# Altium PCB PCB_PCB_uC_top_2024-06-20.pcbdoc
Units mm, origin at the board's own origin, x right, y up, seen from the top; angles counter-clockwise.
Board outline 106.02 x 86.66 mm, 2 copper layers (Top Layer, Bottom Layer); 56 components, 53 nets, 220 pads, 9 vias.
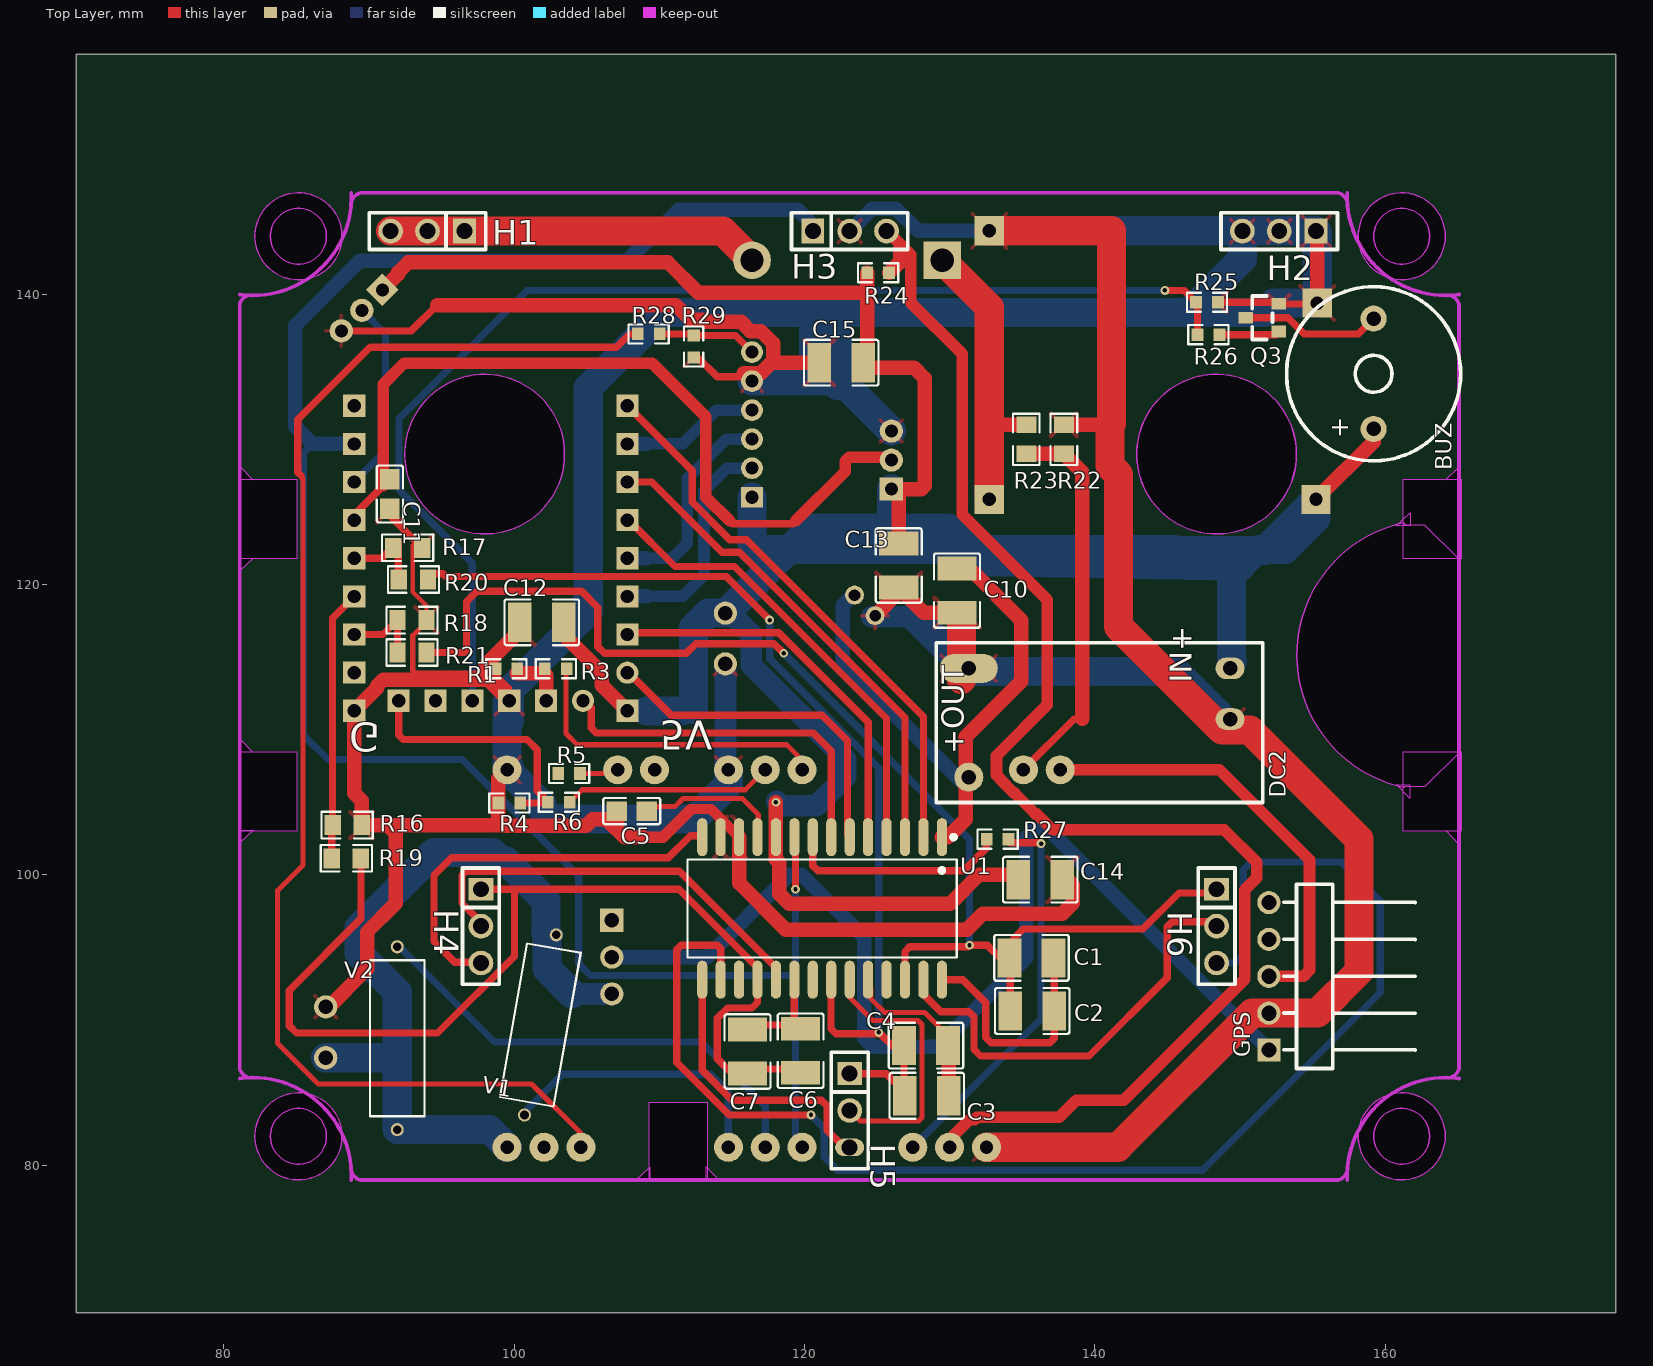
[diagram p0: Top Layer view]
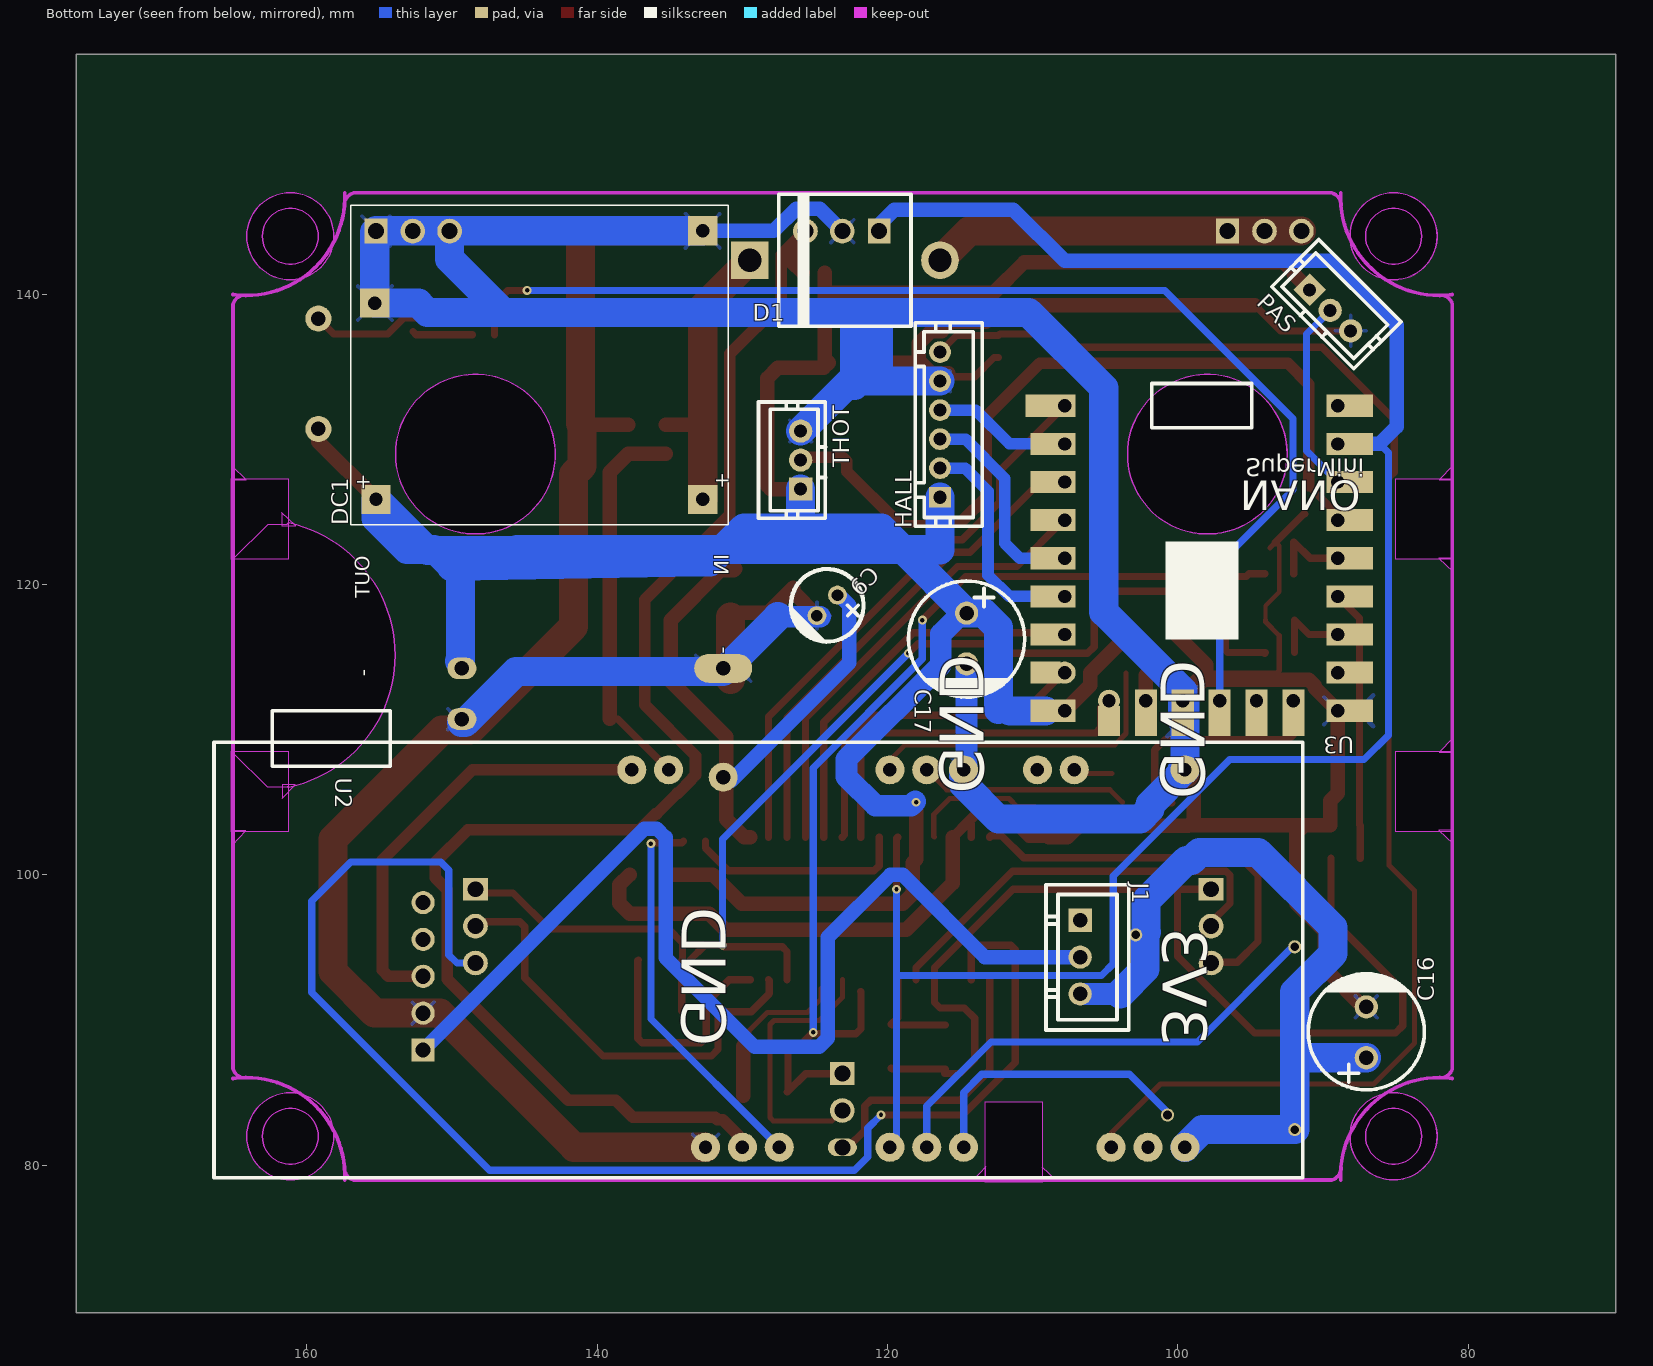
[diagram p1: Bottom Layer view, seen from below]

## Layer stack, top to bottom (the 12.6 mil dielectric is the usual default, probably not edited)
Top Layer: signal copper (thickness not stored)
Dielectric: dielectric 0.32, FR-4, Dk 4.8
Bottom Layer: signal copper (thickness not stored)

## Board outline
175.87,69.85 69.85,69.85 69.85,156.515 175.87,156.515
cut-out: 88.141,81.991 cw(c85.141,81.991) 82.141,81.991 cw(c85.141,81.991)
cut-out: 164.141,143.991 cw(c161.141,143.991) 158.141,143.991 cw(c161.141,143.991)
cut-out: 164.141,81.991 cw(c161.141,81.991) 158.141,81.991 cw(c161.141,81.991)
cut-out: 88.141,143.991 cw(c85.141,143.991) 82.141,143.991 cw(c85.141,143.991)
cut-out: 103.468,128.981 cw(c97.968,128.981) 92.468,128.981 cw(c97.968,128.981)
cut-out: 153.887,128.981 cw(c148.387,128.981) 142.887,128.981 cw(c148.387,128.981)
cut-out: 81.014,127.241 85.014,127.241 85.014,121.772 81.014,121.772
cut-out: 161.246,127.241 165.246,127.241 165.246,121.772 161.246,121.772
cut-out: 109.303,84.322 113.303,84.322 113.303,78.853 109.303,78.853
cut-out: 81.014,108.475 85.014,108.475 85.014,103.006 81.014,103.006
cut-out: 161.246,108.475 165.246,108.475 165.246,103.006 161.246,103.006
cut-out: 159.214,143.991 cw(c161.141,143.991) 163.068,143.991 cw(c161.141,143.991)
cut-out: 83.214,143.991 cw(c85.141,143.991) 87.068,143.991 cw(c85.141,143.991)
cut-out: 83.214,81.991 cw(c85.141,81.991) 87.068,81.991 cw(c85.141,81.991)
cut-out: 159.214,81.991 cw(c161.141,81.991) 163.068,81.991 cw(c161.141,81.991)
cut-out: 161.338,106.07 cw(c161.246,106.158) 161.246,106.031 cw(c161.246,106.158) 161.218,106.034 cw(c163.246,115.138) 153.919,115.138 cw(c163.246,115.138) 161.218,124.242 cw(c161.246,124.118) 161.246,124.245 cw(c161.246,124.118) 161.373,124.123 162.694,124.123 165.088,121.728 165.088,108.416 162.743,106.07
cut-out: 81.991,127.203 81.089,127.203 81.089,128.158
cut-out: 81.057,120.91 81.057,121.813 82.011,121.813
cut-out: 81.057,102.165 81.057,103.067 82.011,103.067
cut-out: 81.985,108.438 81.083,108.438 81.083,109.392
cut-out: 114.142,78.923 113.239,78.923 113.239,79.878
cut-out: 109.342,79.852 109.342,78.949 108.387,78.949
cut-out: 165.12,128.112 165.12,127.209 164.166,127.209
cut-out: 164.191,103.042 165.094,103.042 165.094,102.088
cut-out: 160.794,106.217 161.697,106.217 161.697,105.263
cut-out: 161.723,124.958 161.723,124.055 160.769,124.055

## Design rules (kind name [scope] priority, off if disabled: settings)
BoardOutlineClearance Default [All] p0: genericclearance=0.254 ignorepadtopadclearanceinfootprint=FALSE except(0: Region-OutlineEdge Region-CutoutEdge Arc-SplitContinuation Track-SplitContinuation SMDPad-SplitContinuation THPad-SplitContinuation Via-SplitContinuation Fill-SplitContinuation Poly-SplitContinuation Region-SplitContinuation Text-SplitContinuation; 0.152: Track-OutlineEdge SMDPad-OutlineEdge THPad-OutlineEdge Via-OutlineEdge Fill-OutlineEdge Poly-OutlineEdge Text-OutlineEdge Track-CutoutEdge SMDPad-CutoutEdge THPad-CutoutEdge Via-CutoutEdge Fill-CutoutEdge)
Clearance Default [(InNet('T+') OR InNet('U_L') OR InNet('U_H') OR InNet('UO') OR InNet('V_L') OR InNet('V_H') OR InNet('VO') OR InNet('W_L') OR InNet('W_H') OR InNet('WO') OR InNet('NTC') OR InNet('GND') OR InNet('ISENSE') OR InNet('W_HIN') OR InNet('+5V') OR InNet('UOX') OR InNet('VOX') OR InNet('WOX') OR InNet('THOT') OR InNet('U_LIN') OR InNet('W_LIN') OR InNet('V_HIN') OR InNet('V_LIN') OR InNet('U_HIN') OR InNet('+12V') OR InNet('$1N2961') OR InNet('$1N3241') OR InNet('NRX') OR InNet('NTX') OR InNet('HALT') OR InNet('$1N11348') OR InNet('$1N11342') OR InNet('VSENSE') OR InNet('FAULT') OR InNet('DRX') OR InNet('$1N9478') OR InNet('HALL_W') OR InNet('HALL_V') OR InNet('HALL_U') OR InNet('$1N22834') OR InNet('ENBUZ') OR InNet('$1N22836') OR InNet('$1N27077') OR InNet('$1N27237') OR InNet('+3V3') OR InNet('$1N27595') OR InNet('$1N27524') OR InNet('$1N29131') OR InNet('PAS') OR InNet('TD+') OR InNet('MOTTEMP') OR InNet('$1N29431') OR InNet('GPS+'))] p1: gap=0.178 ignorepadtopadclearanceinfootprint=FALSE except(0: Region-Region Poly-Poly Region-Sheet; 0.152: SMDPad-Fill THPad-Fill Via-Fill Fill-Fill Track-Region SMDPad-Region THPad-Region Via-Region Fill-Region Track-Poly SMDPad-Poly THPad-Poly Via-Poly Fill-Poly Region-Poly Track-Text SMDPad-Text THPad-Text Via-Text Fill-Text Region-Text Poly-Text Text-Text Track-Sheet SMDPad-Sheet THPad-Sheet Via-Sheet Fill-Sheet Poly-Sheet Text-Sheet Track-Hole SMDPad-Hole THPad-Hole Via-Hole Fill-Hole Region-Hole Poly-Hole Text-Hole Sheet-Hole; 0.201: Track-Track Track-SMDPad SMDPad-SMDPad Track-THPad SMDPad-THPad THPad-THPad Track-Via SMDPad-Via THPad-Via Via-Via Track-Fill)
DiffPairsRouting differentialPair [All] p1: maxuncoupledlength=10 minlimit=5.9843 maxlimit=5.9843 mostfreqgap=5.9843 toplayer_minwidth=5 toplayer_prefwidth=10 toplayer_maxwidth=100 bottomlayer_minwidth=5 bottomlayer_prefwidth=10 bottomlayer_maxwidth=100
PasteMaskExpansion Common [All] p1: expansion=0
PlaneConnect Default [All] p1: planeconnectstyle=Relief reliefexpansion=0.508 reliefentries=4 reliefconductorwidth=0 reliefairgap=0.254
PolygonConnect copperRegion [All] p1: connectstyle=Relief reliefentries=4 reliefconductorwidth=11.811 polygonreliefangle="45 Angle" airgapwidth=11.811
PolygonConnect copperRegion1 [All] p1: connectstyle=Relief reliefentries=4 reliefconductorwidth=10 polygonreliefangle="90 Angle" airgapwidth=10
RoutingVias Default [All] p1: viastyle="Through Hole" holewidth=12.0078 minholewidth=12.0078 maxholewidth=2362.0078 width=24.0158 minwidth=24.0158 maxwidth=3937.9922
SolderMaskExpansion Common [All] p1: useseparateexpansions=TRUE expansion=2.0079 expansionbottom=2.0079
Width Default [All] p1: maxlimit=1000 minlimit=10 preferedwidth=10

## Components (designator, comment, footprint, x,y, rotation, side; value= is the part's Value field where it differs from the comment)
BUZ "HMB1275-05B" BUZ-TH_BD12.0-P7.60-D0.6-FD 159.207,134.518 r90 top
C1 "10uF(106) 50V" C1210 135.636,94.285 r0 top
C2 "10uF(106) 50V" C1210 135.687,90.627 r0 top
C3 "10uF(106) 50V" C1210 128.422,84.785 r0 top
C4 "10uF(106) 50V" C1210 128.372,88.24 r0 top
C5 "CC0805KRX7R9BB221" C0805 108.102,104.394 r0 top
C6 "10uF(106) 50V" C1210 119.736,87.884 r90 top
C7 "10uF(106) 50V" C1210 116.078,87.833 r90 top
C9 "RL1J100MC110A00CV0" CAP-TH_BD5.0-P2.00-D0.8-FD 124.155,118.567 r315 bottom
C10 "10uF(106) 50V" C1210 130.505,119.583 r90 top
C11 "30pF/100V" C0805 91.44,126.238 r270 top
C12 "10uF(106) 50V" C1210 101.905,117.399 r0 top
C13 "10uF(106) 50V" C1210 126.492,121.31 r90 top
C14 "10uF(106) 50V" C1210 136.246,99.67 r180 top
C15 "10uF(106) 50V" C1210 122.53,135.28 r0 top
C16 "ERR1CM681F12B35T" CAP-TH_BD8.0-P3.50-D0.6-FD 87.02,89.154 r90 bottom
C17 "ERR1CM681F12B35T" CAP-TH_BD8.0-P3.50-D0.6-FD 114.554,116.281 r270 bottom
D1 "10SQ050" R-6_BD8.9-L8.9-P12.90-D1.3-RD 122.936,142.342 r180 bottom locked
DC1 "LX8015_STEP_DOWN_DC_DC_MODULE" LX8015_STEP_DOWN_DC_DC_MODULE 131.978,125.12 r90 bottom locked
DC2 "DC_STEP_UP_BOOST_MINI_3_12V" dc_step_up_boost_mini_3_12v 131.318,106.731 r90 top
GPS "KH-2.54PH90-1X5P-L13.8" HDR-TH_5P-P2.54-H-M-W10.4-N 151.994,93.015 r90 top
H1 "PZ254-1-03-Z-8.5" HDR-TH_03P-P2.54-V-M 94.031,144.348 r180 top locked
H2 "PZ254-1-03-Z-8.5" HDR-TH_03P-P2.54-V-M 152.705,144.348 r180 top locked
H3 "PZ254-1-03-Z-8.5" HDR-TH_03P-P2.54-V-M 123.114,144.348 r0 top locked
H4 "PZ254-1-03-Z-8.5" HDR-TH_03P-P2.54-V-M 97.714,96.469 r270 top locked
H5 "PZ254-1-03-Z-8.5" hdr-th_03p-p2.54-v-m 123.114,83.769 r270 top locked
H6 "PZ254-1-03-Z-8.5" HDR-TH_03P-P2.54-V-M 148.387,96.469 r270 top locked
HALL "XD-PH-6A-G" CONN-TH_PH-6A_C722783 116.383,131.013 r90 bottom
J1 "ZX-XH2.54-3PZZ" CONN-TH_3P-P2.54_2501S-3P 106.731,94.336 r270 bottom
PAS "XD-PH-3A-G" CONN-TH_3P-P2.00_PH-3AK 89.51,138.887 r225 bottom
Q3 "SI2302" SOT-23_L2.9-W1.3-P1.90-LS2.4-BR 151.536,138.379 r0 top
R1 "0603WAF7502T5E" R0603 99.466,114.198 r180 top
R3 "0603WAF4701T5E" R0603 102.87,114.198 r180 top
R4 "0603WAF1801T5E" R0603 99.67,104.953 r0 top
R5 "0603WAF220JT5E" R0603 103.784,106.985 r180 top
R6 "0603WAF6800T5E" R0603 103.073,105.004 r0 top
R16 "AECR0805F43K0K9" R0805 88.494,103.429 r0 top
R17 "AECR0805F43K0K9" R0805 92.659,122.53 r0 top
R18 "AECR0805F43K0K9" R0805 92.964,117.551 r0 top
R19 "AECR0805F680KK9" R0805 88.443,101.143 r180 top
R20 "AECR0805F680KK9" R0805 93.066,120.345 r180 top
R21 "AECR0805F680KK9" R0805 92.964,115.316 r180 top
R22 "CR0805-FX-1802ELF" R0805 137.871,129.997 r90 top
R23 "AECR0805F680KK9" R0805 135.28,129.997 r270 top
R24 "0603WAF1002T5E" R0603 125.07,141.478 r0 top
R25 "0603WAF4703T5E" R0603 147.726,139.446 r0 top
R26 "0603WAF220JT5E" R0603 147.828,137.211 r0 top
R27 "0603WAF6800T5E" R0603 133.299,102.464 r180 top
R28 "0603WAF6800T5E" R0603 109.271,137.262 r180 top
R29 "0603WAF1801T5E" R0603 112.37,136.398 r270 top
THOT "XD-PH-3A-G" CONN-TH_3P-P2.00_PH-3AK 125.984,128.575 r90 bottom
U1 "6EDL04N06PT" PG-DSO-28_L18.2-W7.6-P1.27-LS10.3-BL 121.209,97.688 r180 top locked
U2 "LILYGO_ESP32_SIM800" LILYLGO_ESO32_SIM800L 137.617,107.239 r270 bottom locked
U3 "Arduino Nano Supermini 24P Small module" arduino_nano_supermini 107.798,111.303 r0 bottom locked
V1 "SW-200D 053" SW-TH_BD3.6-L10.6-LS12.6-D0.4 101.803,89.662 r80 top
V2 "SW-200D 053" SW-TH_BD3.6-L10.6-LS12.6-D0.4 91.948,88.748 r270 top

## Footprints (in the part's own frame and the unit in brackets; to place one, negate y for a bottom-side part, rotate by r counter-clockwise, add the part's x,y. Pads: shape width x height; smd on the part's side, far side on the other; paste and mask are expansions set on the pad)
arduino_nano_supermini [mil]
  rect 60x60 hole 36: 1(-620.28,-27.16) 2(-520.27,-27.16) 3(-420.27,-27.16) 4(-320.27,-27.16) 5(-220.27,-27.17) 7(0,0) 9(0,-206.79) 10(0,-310.19) 11(0,-413.58) 12(0,-516.98) 13(0,-620.37) 14(0,-723.77) 15(0,-827.16) 16(-740.55,0) 17(-740.55,-103.4) 18(-740.55,-206.79) 19(-740.55,-310.19) 20(-740.55,-413.58) 21(-740.55,-516.98) 22(-740.55,-620.37) 23(-740.55,-723.77) 24(-740.55,-827.16)
  rect 60x81.5 smd: 1(-620.27,27.16) 2(-520.27,27.17) 3(-420.27,27.17) 4(-320.27,27.17) 5(-220.27,27.17) 6(-120.27,27.16)
  round 60 hole 36: 6(-120.27,-27.17) 8(0,-103.4)
  rect 81.5x60 smd: 7(51.97,0) 8(51.97,-103.4) 9(51.97,-206.79) 10(51.97,-310.19) 11(51.97,-413.58) 12(51.97,-516.98) 13(51.97,-620.37) 14(51.97,-723.77) 15(65.55,-827.16) 16(-794.88,0) 17(-794.88,-103.4) 18(-794.88,-206.79) 19(-794.88,-310.19) 20(-794.88,-413.58) 21(-794.88,-516.98) 22(-794.88,-620.37) 23(-794.88,-723.77) 24(-794.88,-827.16)
  silkscreen extent -507,-888 -236,-194
BUZ-TH_BD12.0-P7.60-D0.6-FD [mm]
  round 1.8 hole 1: 1(-3.8,0) 2(3.8,0)
  silkscreen extent -6,-6 6,6
C0805 [mm]
  rect 1.41x1.35 smd: 1(-1.03,0) 2(1.03,0)
  silkscreen extent -1.96,-0.9 1.96,0.9
C1210 [mm]
  rect 1.635x2.7 smd: 1(-1.517,0) 2(1.517,0)
  silkscreen extent -2.56,-1.58 2.56,1.58
CAP-TH_BD5.0-P2.00-D0.8-FD [mm]
  round 1.3 hole 0.8: 1(-1,0) 2(1,0)
  silkscreen extent -2.5,-2.5 2.5,2.5
CAP-TH_BD8.0-P3.50-D0.6-FD [mm]
  round 1.6 hole 1: 1(-1.75,0) 2(1.75,0)
  silkscreen extent -3.96,-4 4.04,4
CONN-TH_3P-P2.00_PH-3AK [mm]
  rect 1.6x1.6 hole 0.9: 1(-2,0)
  round 1.6 hole 0.9: 2(0,0) 3(2,0)
  silkscreen extent -4.01,-1.71 4.01,2.9
CONN-TH_3P-P2.54_2501S-3P [mm]
  rect 1.6x1.6 hole 1: 1(-2.54,0)
  round 1.6 hole 1: 2(0,0) 3(2.54,0)
  silkscreen extent -4.98,-2.35 5.02,3.35
CONN-TH_PH-6A_C722783 [mm]
  rect 1.4x1.5 hole 0.9: 1(-5,0)
  round 1.5 hole 0.9: 2(-3,0) 3(-1,0) 4(1,0) 5(3,0) 6(5,0)
  silkscreen extent -7,-2.9 7.01,1.7
dc_step_up_boost_mini_3_12v [mm]
  oval 1.5x2 hole 1: 1(7.5,-18) 2(4,-18)
  round 2 hole 1: 3(0,0)
  oval 2x4 hole 1: 4(7.5,0)
  silkscreen extent -1.75,-20.25 9.25,2.25
HDR-TH_03P-P2.54-V-M [mm]
  rect 1.575x1.7 hole 1.1: 1(-2.54,0)
  round 1.7 hole 1.1: 2(0,0) 3(2.54,0)
  silkscreen extent -4.01,-1.27 4.01,1.27
hdr-th_03p-p2.54-v-m [mm]
  rect 1.575x1.7 hole 1.1: 1(-2.54,0)
  round 1.7 hole 1.1: 2(0,0)
  oval 1.2x2 hole 1.1: 3(2.54,0)
  silkscreen extent -4.01,-1.27 4.01,1.27
HDR-TH_5P-P2.54-H-M-W10.4-N [mm]
  rect 1.6x1.6 hole 1.05: 1(-5.08,0)
  round 1.6 hole 1.05: 2(-2.54,0) 3(0,0) 4(2.54,0) 5(5.08,0)
  silkscreen extent -6.35,-10.08 6.35,-1.03
LILYLGO_ESO32_SIM800L [mm]
  round 2 hole 0.914: 1(0,30.48) 2(0,2.54) 3(0,27.94) 12(26,7.62) 14(26,10.16) 15(0,0) 18(0,17.78) 19(0,20.32) 25(26,17.78) 32(26,22.86) 33(26,20.32) 36(26,33.02) 40(26,38.1) 41(26,35.56) 42(26,5.08) 60(0,38.1) 61(0,22.86)
  silkscreen extent -4.06,-28.77 28.1,46.23
LX8015_STEP_DOWN_DC_DC_MODULE [mm]
  rect 2x2 hole 0.914: 1(0.75,0.75) 2(19.25,0.75) 3(0.75,23.25) 4(14.262,23.343)
  silkscreen extent -1,-1 21,25
PG-DSO-28_L18.2-W7.6-P1.27-LS10.3-BL [mm]
  oval 0.7x2.62 smd: 1(-8.255,-4.91) 2(-6.985,-4.91) 3(-5.715,-4.91) 4(-4.445,-4.91) 5(-3.175,-4.91) 6(-1.905,-4.91) 7(-0.635,-4.91) 8(0.635,-4.91) 9(1.905,-4.91) 10(3.175,-4.91) 11(4.445,-4.91) 12(5.715,-4.91) 13(6.985,-4.91) 14(8.255,-4.91) 15(8.255,4.91) 16(6.985,4.91) 17(5.715,4.91) 18(4.445,4.91) 19(3.175,4.91) 20(1.905,4.91) 21(0.635,4.91) 22(-0.635,4.91) 23(-1.905,4.91) 24(-3.175,4.91) 25(-4.445,4.91) 26(-5.715,4.91) 27(-6.985,4.91) 28(-8.255,4.91)
  silkscreen extent -9.28,-5.06 9.28,3.37
R0603 [mm]
  rect 0.806x0.864 smd: 1(-0.753,0) 2(0.753,0)
  silkscreen extent -1.39,-0.66 1.39,0.66
R0805 [mm]
  rect 1.133x1.377 smd: 1(-1,0) 2(1,0)
  silkscreen extent -1.76,-0.92 1.76,0.92
R-6_BD8.9-L8.9-P12.90-D1.3-RD [mm]
  rect 2.6x2.6 hole 1.6: 1(-6.55,0)
  round 2.6 hole 1.6: 2(6.55,0)
  silkscreen extent -4.55,-4.55 4.55,4.55
SOT-23_L2.9-W1.3-P1.90-LS2.4-BR [mm]
  rect 1x0.8 smd: 1(1.15,-0.95) 2(1.15,0.95) 3(-1.15,0)
  silkscreen extent -0.7,-1.5 0.7,1.5
SW-TH_BD3.6-L10.6-LS12.6-D0.4 [mm]
  round 0.9 hole 0.6: 1(-6.3,0) 2(6.3,0)
  silkscreen extent -5.38,-1.88 5.38,1.88

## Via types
v1: diameter 0.61, hole 0.305, Top Layer to Bottom Layer, 9 vias

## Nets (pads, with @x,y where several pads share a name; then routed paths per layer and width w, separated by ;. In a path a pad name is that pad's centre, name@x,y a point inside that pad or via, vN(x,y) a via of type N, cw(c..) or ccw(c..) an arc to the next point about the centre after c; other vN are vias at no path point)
$1N2961: C1.2 C2.2 U1.28 | length 16.5
  Top Layer w0.5: U1.28 130.896,92.778 132.488,91.186 132.488,88.796 132.842,88.443 136.906,88.443 137.204,88.741 C2.2 137.204,94.082 C1.2@137.153,94.132
$1N3241: C5.2 U1.11 | length 10.2
  Top Layer w0.35: C5.2 109.336,104.394 109.437,104.292 109.844,104.699 111.07,104.699 111.635,105.263 112.112,105.263 112.12,105.271 113.846,105.271 113.855,105.263 115.717,105.263 116.815,104.165 116.815,102.649 U1.11
$1N9478: R1.1 R3.2 U3.5 | length 3.9
  Top Layer w1: R1.1@100.169,113.894 102.066,113.894 102.203,113.757 U3.5@102.203,111.993
$1N11342: C6.2 C7.2 U1.20 | length 7
  Top Layer w0.5: C7.2@116.027,89.655 119.685,89.655 119.736,89.706 119.304,90.138 U1.20
$1N11348: C3.2 C4.2 U1.24 | length 11.6
  Top Layer w0.35: U1.24 124.384,92.372 124.573,92.183 124.573,91.467 125.526,90.515 128.281,90.515 129.539,89.257 129.539,88.894 C4.2@129.889,88.544
  Top Layer w1: C4.2 129.94,88.189 C3.2
$1N22834: Q3.1 R26.2 | length 4.2
  Top Layer w0.5: R26.2 152.468,137.211 Q3.1
$1N22836: BUZ.2 Q3.3 | length 9.7
  Top Layer w0.5: Q3.3 153.314,138.379 154.432,137.262 158.15,137.262 BUZ.2
$1N27077: R5.1 U2.1 | length 2.7
  Top Layer w0.35: R5.1 106.883,106.985 U2.1
$1N27237: R6.2 U2.19 | length 14.4
  Top Layer w0.35: R6.2 104.687,105.864 115.922,105.864 U2.19
$1N27524: U2.32 V1.1 | length 19.6
  Bottom Layer w0.5: V1.1 100.709,83.64 103.327,86.258 113.514,86.258 114.757,85.015 U2.32
$1N27595: R27.1 U2.14 | length 26.9
  Top Layer w0.5: R27.1@134.053,102.311 134.154,102.21 136.246,102.21 v1(136.296,102.159)
  Bottom Layer w0.5: U2.14 136.296,90.078 v1(136.296,102.159)
$1N29131: U2.33 V2.1 | length 32.7
  Bottom Layer w0.5: V2.1 92.1,95.048 98.654,88.494 112.878,88.494 117.297,84.074 U2.33
$1N29431: HALL.6 R28.1 R29.1 | length 6.9
  Top Layer w0.5: R28.1 112.259,137.262 R29.1 115.245,137.151 HALL.6
+3V3: C16.1 J1.3 U2.40 V1.2 V2.2 | length 55.1
  Bottom Layer w1: 102.157,96.069 102.159,96.068 102.26,95.966 102.36,95.866 V1.2
  Bottom Layer w1.5: 103.988,91.796 J1.3
  Bottom Layer w2: C16.1 91.84,87.404 91.948,87.296 ; U2.40 98.308,82.448 V2.2 91.948,87.296 ; 102.159,96.068 102.21,96.118 102.21,98.203 99.416,100.997 99.061,100.997 98.512,101.546 94.484,101.546 89.306,96.368 89.306,94.59 91.948,91.948 91.948,87.296 ; 102.26,95.966 102.26,93.523 103.988,91.796
+5V: BUZ.1 C12.2 C13.2 C14.2 C15.2 C17.1 DC1.3 DC2.1 HALL.1 PAS.1 R24.1 THOT.1 U1.10 U3.7 | length 232
  Top Layer w1: PAS.1 91.999,141.376 91.999,141.478 92.706,142.185 110.596,142.185 112.683,140.098 124.316,140.098 ; C12.2@103.27,116.688 106.036,113.922 106.036,113.065 U3.7@107.798,111.303 ; v1(118.034,105.004) U1.10 118.034,101.067 118.254,100.847 118.254,98.714 118.964,98.004 130.029,98.004 132.05,100.025 C14.2@134.728,100.025 ; R24.1 124.316,140.098 ; C13.2 126.492,126.067 THOT.1 128.048,126.575 128.27,126.797 128.27,134.214 127.563,134.921 124.407,134.921 C15.2 124.316,135.55 124.316,140.098 ; DC1.3@155.228,125.87 159.207,129.849 BUZ.1
  Bottom Layer w1: U3.7@107.798,111.303 U3.7@109.118,111.303
  Bottom Layer w1.5: C17.1@114.887,118.031 116.332,116.586 116.332,114.452 122.829,107.956 122.829,106.761 120.823,104.755 118.384,104.755 v1@118.085,105.054
  Bottom Layer w2: U3.7@109.118,111.303 111.557,111.303 ; 112.37,111.404 112.37,117.043 113.358,118.031 C17.1 ; C17.1@114.91,118.031 114.887,118.031 C17.1 ; HALL.1@116.383,126.013 116.383,122.377 116.43,122.424 118.947,122.424 ; THOT.1 125.984,123.901 ; 132.842,121.564 132.74,121.564 ; DC2.1@149.47,114.739 149.42,114.79 149.42,120.722 149.958,121.261 150.008,121.261 ; 150.063,121.26 150.009,121.261 ; 151.142,122.329 151.237,122.424 151.782,122.424 ; 151.989,122.631 155.228,125.87 155.228,124.545 153.107,122.424 151.989,122.424 ; C17.1 118.947,122.424 ; 118.947,122.424 126.026,122.424 ; 118.947,122.424 120.424,123.901 125.984,123.901 ; 125.984,123.901 129.896,123.901 131.373,122.424 ; 125.984,123.901 125.984,122.466 126.026,122.424 ; 126.026,122.424 131.373,122.424 ; 131.373,122.424 132.232,121.564 132.74,121.564 ; 131.373,122.424 145.537,122.424 145.631,122.329 151.077,122.329 ; 132.74,121.564 150.008,121.261 ; 150.009,121.261 151.077,122.329 ; 151.077,122.329 151.687,122.329 ; 151.687,122.329 151.782,122.424 ; 151.687,122.329 151.989,122.424 ; 151.782,122.424 151.989,122.424
+12V: C9.1 C10.2 DC2.3 U1.1 | length 40.6
  Top Layer w1: U1.1 129.87,102.598 131.115,103.843 131.115,109.525 134.925,113.335 134.925,117.551 131.477,120.999 130.607,120.999 C10.2
  Bottom Layer w1: C9.1 123.338,119.274 122.635,118.571 122.635,114.601 130.759,106.477 131.064,106.477 DC2.3
DRX: GPS.3 U2.15 | length 30.3
  Top Layer w0.8: U2.15 148.59,107.239 154.788,101.041 154.788,93.421 154.381,93.015 GPS.3
ENBUZ: R25.1 R26.1 U3.3 | length 82.7
  Top Layer w0.5: v1(144.831,140.261) 146.158,140.261 R25.1 147.075,139.344 R26.1
  Bottom Layer w0.5: U3.3@97.123,111.993 97.123,121.48 92.066,126.537 92.066,131.426 100.901,140.261 v1(144.831,140.261)
FAULT: R27.2 U1.8 | length 15.2
  Top Layer w0.5: U1.8 120.574,100.635 120.927,100.281 130.962,100.281 132.546,101.865 R27.2@132.546,102.311
GND: C5.1 C9.2 C10.1 C11.2 C12.1 C13.1 C14.1 C15.1 C16.2 C17.2 DC1.2 DC1.4 DC2.2 DC2.4 GPS.2 H2.1 H2.2 H2.3 H3.2 HALL.5 PAS.3 Q3.2 R1.2 R4.1 R16.2 R17.2 R18.2 R22.2 R25.2 R29.2 THOT.3 U1.12 U1.13 U2.42 U2.60 U2.61 U3.4 U3.16 | length 497.1
  Top Layer w0.3: R17.2@93.218,122.885 93.006,122.673 93.006,119.498 93.964,118.54 R18.2
  Top Layer w0.35: R17.2@93.304,122.885 R17.2 ; R18.2 93.964,117.429 93.015,116.48 93.015,114.097 93.218,113.894 98.662,113.894 99.663,112.893 U3.4@99.663,111.993
  Top Layer w0.5: PAS.3 92.917,137.473 94.698,139.255 ; C11.2@91.237,124.852 91.336,124.852 93.304,122.885 R17.2@93.218,122.885 ; R29.2 112.666,135.645 113.995,134.315 HALL.5@116.081,134.315 ; U1.13 114.224,103.505 U1.13@114.406,103.687 ; R25.2 152.57,139.446 Q3.2 155.433,139.329 DC1.4@155.55,139.446
  Top Layer w0.7: 112.42,104.546 113.546,104.546 114.406,103.687 U1.12
  Top Layer w0.8: 108.885,102.586 110.257,102.586 112.152,104.481 ; C10.1 C10.1@130.81,117.761
  Top Layer w1: C16.2@87.016,90.674 89.865,93.523 89.865,96.063 91.846,98.044 91.846,102.87 91.288,103.429 ; 94.698,139.255 111.141,139.255 112.141,138.255 113.092,138.255 113.245,138.101 115.638,138.101 116.276,137.463 116.983,137.463 117.833,136.614 117.833,135.413 117.701,135.28 ; 98.035,113.955 98.035,114.488 C12.1@100.235,116.688 ; U2.60 98.916,106.638 R4.1 98.916,103.734 99.221,103.429 ; U3.4@99.663,111.993 98.201,113.455 90.991,113.455 90.581,113.045 90.581,112.896 88.988,111.303 88.988,105.623 89.494,105.117 R16.2 91.288,103.429 ; C5.1@107.123,103.835 C5.1@106.564,103.835 ; 108.885,102.586 107.61,102.586 106.564,103.632 C5.1@106.564,103.835 ; U1.12 115.494,99.441 118.703,96.232 131.182,96.232 132.283,97.333 137.77,97.333 138.477,98.04 138.477,99.311 C14.1@137.763,100.025 ; HALL.5 116.081,134.315 115.833,134.563 116.983,134.563 117.701,135.28 ; C15.1 117.701,135.28 ; C9.2 126.492,119.49 C13.1 128.219,118.066 C10.1 ; R22.2 141.052,130.997 ; H2.1 155.321,144.272 DC1.4 ; 91.288,103.429 99.221,103.429 ; 99.221,103.429 99.27,103.38 104.964,103.38 105.419,103.835 C5.1@106.564,103.835
  Top Layer w2: DC2.4@130.81,113.469 C10.1@130.81,117.761 ; U2.42 141.589,81.239 150.825,90.475 GPS.2 152.006,90.487 155.343,90.487 158.188,93.332 158.188,102.476 150.682,109.981 150.127,109.981 148.76,109.981 141.627,117.114 141.627,127.587 141.048,128.165 141.048,130.994 141.052,130.997 141.144,131.089 141.144,144.37 DC1.2
  Bottom Layer w1: H3.2 124.664,145.898 126.296,145.898 127.824,144.37 DC1.2
  Bottom Layer w1.5: C17.2 114.554,107.442 U2.61 ; C9.2@124.634,117.784 127.562,117.784
  Bottom Layer w2: U2.60@99.663,107.384 U2.60 ; U3.4@99.663,110.613 U3.4@99.663,111.993 ; U2.61 114.757,106.227 112.37,103.839 102.612,103.839 101.905,104.546 101.905,104.851 U2.60 ; HALL.5 120.623,134.013 ; 122.276,133.706 122.276,134.013 ; THOT.3 122.546,134.013 122.276,134.013 ; 127.562,117.784 131.343,114.002 145.593,114.002 149.093,110.502 DC2.2@149.343,110.502 ; DC1.2 155.223,144.37 H2.1 155.321,144.272 DC1.4 152.321,139.382 151.673,138.735 146.473,138.735 ; H2.3 150.165,142.427 146.473,138.735 ; U2.60 99.517,111.847 U3.4@99.663,111.993 ; U3.4@99.663,111.993 99.663,112.674 105.105,118.116 105.105,133.553 110.287,138.735 120.623,138.735 ; 120.623,134.013 120.623,138.735 ; 120.623,134.013 122.276,134.013 ; 120.623,138.735 122.358,138.735 ; 122.276,134.013 122.276,138.652 122.358,138.735 ; 122.358,138.735 146.473,138.735
GPS+: GPS.1 J1.2 | length 74
  Bottom Layer w1: J1.2 113.285,94.336 118.964,100.014 119.796,100.014 124.115,95.695 124.115,88.738 124.704,88.149 129.16,88.149 135.291,94.281 135.291,102.575 135.88,103.164 136.765,103.164 GPS.1
HALL_U: HALL.2 U3.10 | length 15.6
  Bottom Layer w0.8: U3.10@109.118,119.182 111.612,119.182 113.081,120.65 113.081,126.438 114.656,128.013 HALL.2
  Bottom Layer w1: U3.10@107.798,119.182 U3.10@109.118,119.182
HALL_V: HALL.3 U3.11 | length 14.6
  Bottom Layer w0.8: U3.11@109.118,121.808 110.886,121.808 111.912,122.834 111.912,127.305 114.621,130.013 HALL.3
  Bottom Layer w1: U3.11@107.798,121.808 U3.11@109.118,121.808
HALL_W: HALL.4 U3.14 | length 9.5
  Bottom Layer w0.8: U3.14@109.118,129.687 111.602,129.687 113.928,132.013 HALL.4
  Bottom Layer w1: U3.14@107.798,129.687 U3.14@109.118,129.687
HALT: R3.1 U2.18 | length 21.8
  Top Layer w0.35: R3.1@103.573,113.894 103.573,109.737 104.343,108.966 118.77,108.966 119.837,107.899 U2.18
ISENSE: H3.1 U1.9 U2.25 U3.23 | length 137.6
  Top Layer w0.5: U1.9 119.38,102.522 v1(119.38,99.009)
  Bottom Layer w0.5: 86.108,129.687 85.496,129.075 85.496,109.626 87.173,107.95 96.418,107.95 104.445,99.924 104.445,93.878 105.256,93.068 119.388,93.068 ; v1(119.38,99.009) 119.38,93.365 119.388,93.357 119.388,93.068 ; U2.25 119.38,81.696 119.38,93.06 119.388,93.068
  Bottom Layer w1: U3.23@88.988,129.687 87.608,129.687 86.108,129.687 86.108,129.69 84.938,130.861 84.938,137.871 89.357,142.291 107.798,142.291 111.328,145.821 119.532,145.821 120.675,144.678 120.675,144.45 H3.1
MOTTEMP: R28.2 U2.36 | length 94
  Top Layer w0.35: 85.341,127.376 85.442,127.275 85.442,100.648 83.7,98.905 83.7,88.41 86.512,85.598 101.194,85.598 104.597,82.194 U2.36
  Top Layer w0.5: 85.345,127.478 85.087,127.736 85.087,131.366 90.068,136.347 107.044,136.347 107.959,137.262 R28.2
NRX: R5.2
NTC: H3.3 R24.2 U2.12 | length 99.8
  Top Layer w0.8: H3.3 125.705,144.348 127.332,142.721 127.332,139.419 130.863,135.888 130.863,124.826 136.727,118.962 136.727,111.71 133.223,108.206 133.223,106.881 133.477,106.627 133.477,106.576 134.414,105.639 134.465,105.639 135.913,104.191 136.001,104.191 137.096,103.096 148.923,103.096 151.16,100.859 151.16,99.8 150.34,98.979 150.34,92.811 141.997,84.469 138.713,84.469 137.541,83.296 131.874,83.296 131.722,83.144 131.343,83.144 129.997,81.798 U2.12
  Top Layer w1: R24.2 126.594,142.249 126.594,143.104
NTX: R4.2 R6.1 U3.1 | length 18.2
  Top Layer w0.5: U3.1@92.043,111.993 92.043,109.633 92.354,109.322 100.889,109.322 101.6,108.61 101.6,105.774 102.32,105.054 R6.1 102.269,104.953 R4.2
PAS: PAS.2 U3.22 | length 13.4
  Bottom Layer w0.5: U3.22@88.988,127.06 91.135,129.208 91.135,137.262 PAS.2
T+: D1.2 H1.1 H1.2 H1.3 | length 25.7
  Top Layer w2: H1.3 H1.2 H1.1 114.38,144.348 D1.2
TD+: D1.1 DC1.1 R23.1 | length 20.4
  Top Layer w1: 132.728,130.891 132.835,130.997 R23.1
  Top Layer w2: D1.1 132.728,139.099 132.728,130.891 DC1.1
THOT: C11.1 THOT.2 U3.21 | length 56
  Top Layer w0.5: U3.21@88.988,124.663 88.988,124.816 C11.1@90.983,126.811 ; 114.848,124.386 115.043,124.19 119.212,124.19 119.407,124.386
  Top Layer w0.8: U3.21@88.892,124.66 88.892,124.529 U3.21@88.988,124.434 ; C11.1@90.983,126.811 90.983,127.014 90.983,133.807 92.412,135.236 109.522,135.236 113.21,131.549 113.21,126.024 114.848,124.386 ; 119.407,124.386 122.811,127.789 122.811,128.497 123.092,128.778 125.628,128.778 125.832,128.575 THOT.2
U_H: H4.2 U1.19 | length 29.4
  Top Layer w0.5: H4.2 97.714,96.735 96.414,98.035 96.414,99.983 96.677,100.247 111.387,100.247 118.034,93.6 U1.19
U_HIN: U1.4 U3.12 | length 31.6
  Top Layer w0.5: U3.12@107.899,124.434 111.085,121.248 115.175,121.248 125.654,110.769 U1.4
U_L: H4.3 U1.14 | length 28.1
  Top Layer w0.5: H4.3 97.663,93.98 95.91,93.98 94.48,95.411 94.48,99.966 95.69,101.176 110.617,101.176 112.141,102.7 112.903,102.7 112.954,102.649 U1.14
U_LIN: U1.7 U3.6 | length 25.2
  Top Layer w0.5: U3.6@104.844,111.993 105.31,111.527 105.31,110.13 105.664,109.777 120.601,109.777 121.844,108.534 U1.7
UO: C6.1 C7.1 H4.1 R19.1 U1.18 | length 72
  Top Layer w0.5: R19.1 89.443,96.984 84.502,92.043 84.502,89.603 85.002,89.103 94.726,89.103 100.022,94.399 100.022,99.009 ; H4.1 100.022,99.009 ; C7.1@116.027,86.621 119.685,86.621 C6.1@119.736,86.671 ; C7.1 115.005,86.316 113.995,87.325 113.995,90.119 114.706,90.83 116.383,90.83 116.764,91.211 U1.18 116.764,93.6 111.354,99.009 100.022,99.009
UOX: R16.1 R19.2 U3.19 | length 18.7
  Top Layer w0.5: R19.2 87.443,103.378 R16.1 87.494,117.688 U3.19@88.988,119.182
V_H: H5.2 U1.23 | length 18.8
  Top Layer w0.35: H5.2 123.823,83.06 127.878,83.06 128.098,83.28 128.098,89.694 127.827,89.965 124.708,89.965 123.114,91.559 U1.23
V_HIN: U1.3 U3.13 | length 34.1
  Top Layer w0.5: U3.13@107.798,127.06 109.482,127.06 114.32,122.222 115.522,122.222 126.924,110.82 U1.3
V_L: H5.3 U1.15 | length 19.6
  Top Layer w0.5: U1.15 112.954,86.538 115.011,84.48 121.158,84.48 121.564,84.074 121.564,82.398 122.733,81.229 H5.3
V_LIN: U1.6 U3.8 | length 23.7
  Top Layer w0.5: U3.8@107.899,113.929 110.83,110.998 121.209,110.998 122.961,109.245 122.961,102.751 U1.6
VO: C3.1 C4.1 H5.1 R20.1 U1.22 | length 71.2
  Top Layer w0.5: R20.1@94.015,120.752 95.081,120.752 95.284,120.548 114.605,120.548 v1(117.602,117.551) ; U1.22@121.844,91.966 121.82,91.942 121.82,89.406 122.174,89.052 125.229,89.052 126.304,87.977 C4.1@126.558,87.977 ; H5.1 125.635,86.309 C3.1@126.854,85.09 ; C4.1@126.854,87.681 C3.1@126.854,85.09 ; C3.1@126.905,85.039 C3.1@126.854,85.09
  Bottom Layer w0.5: v1(117.602,117.551) 117.602,114.879 125.12,107.361 v1(125.12,89.154)
VOX: R17.1 R20.2 U3.20 | length 5.7
  Top Layer w0.5: U3.20@88.988,121.808 90.887,121.808 92.015,122.936 R20.2@92.015,120.752
VSENSE: R22.1 R23.2 U2.2 | length 26.9
  Top Layer w0.5: U2.2 138.582,110.744 139.141,110.744
  Top Layer w1: R23.2 R22.1 139.141,127.727 139.141,110.744
W_H: H6.2 U1.27 | length 30.3
  Top Layer w0.5: U1.27 128.143,92.728 128.143,91.821 129.388,90.576 131.318,90.576 131.672,90.223 131.672,87.986 132.129,87.528 139.598,87.528 144.983,92.913 144.983,96.418 145.337,96.772 147.982,96.772 148.285,96.469 H6.2
W_HIN: U1.2 U3.15 | length 38.8
  Top Layer w0.5: U3.15@107.798,132.313 112.268,127.842 112.268,125.679 114.859,123.088 116.006,123.088 128.194,110.901 U1.2
W_L: H6.3 U1.16 | length 95.9
  Top Layer w0.5: U1.16 114.224,94.92 113.995,95.148 111.506,95.148 111.201,94.844 111.201,87.071 114.808,83.464 v1(120.447,83.464)
  Bottom Layer w0.5: v1(120.447,83.464) 121.361,82.55 121.361,80.569 122.276,79.654 147.422,79.654 159.664,91.897 159.664,98.196 156.972,100.889 150.774,100.889 150.216,100.33 150.216,94.488 149.657,93.929 H6.3
W_LIN: U1.5 U3.9 | length 27
  Top Layer w0.5: U3.9@107.899,116.555 108.02,116.676 118.224,116.676 124.384,110.516 U1.5
WO: C1.1 C2.1 H6.1 R21.1 U1.26 | length 87.4
  Top Layer w0.5: R21.1@94.015,115.265 R21.1 96.571,115.316 96.723,115.468 96.723,118.821 97.434,119.532 104.648,119.532 105.766,118.415 105.766,115.722 106.223,115.265 111.862,115.265 112.522,115.926 117.907,115.926 v1(118.567,115.265) ; U1.26 126.924,94.717 127.254,95.047 131.267,95.047 v1(131.369,95.148) 132.595,95.148 C1.1@133.611,94.132 ; C2.1 134.169,94.082 134.119,94.132 134.119,95.307 135.077,96.266 143.307,96.266 145.796,98.755 148.133,98.755 H6.1
  Bottom Layer w0.5: v1(118.567,115.265) 131.369,102.464 v1(131.369,95.148)
WOX: R18.1 R21.2 U3.18 | length 5.6
  Top Layer w0.5: U3.18@88.988,116.555 90.968,116.555 R18.1 R21.2
pads on no net: GPS.4 GPS.5 J1.1 U1.17 U1.21 U1.25 U2.3 U2.41 U3.2 U3.17 U3.24

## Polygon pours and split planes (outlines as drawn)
GND on Bottom Layer (solid, remove dead copper, pour order 2): 77.978,147.625 167.792,147.625 167.792,78.588 77.978,78.588
GND on Top Layer (solid, remove dead copper, pour order 0): 76.2,150.165 169.52,150.165 169.52,76.2 76.2,76.2

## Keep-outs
Board Outline Layer:
  circle w0.025: c85.141,81.991 r3
  region: 88.141,81.991 cw(c85.141,81.991) 82.141,81.991 cw(c85.141,81.991)
  circle w0.025: c161.141,143.991 r3
  region: 164.141,143.991 cw(c161.141,143.991) 158.141,143.991 cw(c161.141,143.991)
  circle w0.025: c161.141,81.991 r3
  region: 164.141,81.991 cw(c161.141,81.991) 158.141,81.991 cw(c161.141,81.991)
  circle w0.025: c85.141,143.991 r3
  region: 88.141,143.991 cw(c85.141,143.991) 82.141,143.991 cw(c85.141,143.991)
  circle w0.025: c97.968,128.981 r5.5
  region: 103.468,128.981 cw(c97.968,128.981) 92.468,128.981 cw(c97.968,128.981)
  circle w0.025: c148.387,128.981 r5.5
  region: 153.887,128.981 cw(c148.387,128.981) 142.887,128.981 cw(c148.387,128.981)
  region: 81.014,127.241 85.014,127.241 85.014,121.772 81.014,121.772
  region: 161.246,127.241 165.246,127.241 165.246,121.772 161.246,121.772
  region: 109.303,84.322 113.303,84.322 113.303,78.853 109.303,78.853
  region: 81.014,108.475 85.014,108.475 85.014,103.006 81.014,103.006
  region: 161.246,108.475 165.246,108.475 165.246,103.006 161.246,103.006
  region: 159.214,143.991 cw(c161.141,143.991) 163.068,143.991 cw(c161.141,143.991)
  region: 83.214,143.991 cw(c85.141,143.991) 87.068,143.991 cw(c85.141,143.991)
  region: 83.214,81.991 cw(c85.141,81.991) 87.068,81.991 cw(c85.141,81.991)
  region: 159.214,81.991 cw(c161.141,81.991) 163.068,81.991 cw(c161.141,81.991)
  region: 161.338,106.07 cw(c161.246,106.158) 161.246,106.031 cw(c161.246,106.158) 161.218,106.034 cw(c163.246,115.138) 153.919,115.138 cw(c163.246,115.138) 161.218,124.242 cw(c161.246,124.118) 161.246,124.245 cw(c161.246,124.118) 161.373,124.123 162.694,124.123 165.088,121.728 165.088,108.416 162.743,106.07
  region: 81.991,127.203 81.089,127.203 81.089,128.158
  region: 81.057,120.91 81.057,121.813 82.011,121.813
  region: 81.057,102.165 81.057,103.067 82.011,103.067
  region: 81.985,108.438 81.083,108.438 81.083,109.392
  region: 114.142,78.923 113.239,78.923 113.239,79.878
  region: 109.342,79.852 109.342,78.949 108.387,78.949
  region: 165.12,128.112 165.12,127.209 164.166,127.209
  region: 164.191,103.042 165.094,103.042 165.094,102.088
  region: 160.794,106.217 161.697,106.217 161.697,105.263
  region: 161.723,124.958 161.723,124.055 160.769,124.055
  lines w0.025: 81.057,103.067 81.057,102.165 82.011,103.067 81.057,103.067 ; 81.057,103.067 81.057,103.067 ; 81.057,121.813 81.057,120.91 82.011,121.813 81.057,121.813 ; 81.057,121.813 81.057,121.813 ; 81.083,108.438 81.985,108.438 81.083,109.392 81.083,108.438 ; 81.083,108.438 81.083,108.438 ; 81.089,127.203 81.991,127.203 81.089,128.158 81.089,127.203 ; 81.089,127.203 81.089,127.203 ; 109.342,78.949 109.342,79.852 108.387,78.949 109.342,78.949 ; 109.342,78.949 109.342,78.949 ; 113.239,78.923 114.142,78.923 113.239,79.878 113.239,78.923 ; 113.239,78.923 113.239,78.923 ; 161.697,106.217 160.794,106.217 161.697,105.263 161.697,106.217 ; 161.697,106.217 161.697,106.217 ; 161.723,124.055 161.723,124.958 160.769,124.055 161.723,124.055 ; 161.723,124.055 161.723,124.055 ; 165.094,103.042 164.191,103.042 165.094,102.088 165.094,103.042 ; 165.094,103.042 165.094,103.042 ; 165.12,127.209 165.12,128.112 164.166,127.209 165.12,127.209 ; 165.12,127.209 165.12,127.209 ; 81.014,103.006 85.014,103.006 85.014,108.475 81.014,108.475 81.014,103.006 ; 81.014,121.772 85.014,121.772 85.014,127.241 81.014,127.241 81.014,121.772 ; 83.214,81.991 cw(c85.141,81.991) 87.068,81.991 cw(c85.141,81.991) 83.214,81.991 ; 83.214,143.991 cw(c85.141,143.991) 87.068,143.991 cw(c85.141,143.991) 83.214,143.991 ; 109.303,78.853 113.303,78.853 113.303,84.322 109.303,84.322 109.303,78.853 ; 153.919,115.138 ccw(c163.246,115.138) 161.218,106.034 ccw(c161.246,106.158) 161.246,106.031 ccw(c161.246,106.158) 161.338,106.07 162.743,106.07 165.088,108.416 165.088,121.728 162.694,124.123 161.373,124.123 ccw(c161.246,124.118) 161.246,124.245 ccw(c161.246,124.118) 161.218,124.242 ccw(c163.246,115.138) 153.919,115.138 ; 159.214,81.991 cw(c161.141,81.991) 163.068,81.991 cw(c161.141,81.991) 159.214,81.991 ; 159.214,143.991 cw(c161.141,143.991) 163.068,143.991 cw(c161.141,143.991) 159.214,143.991 ; 161.246,103.006 165.246,103.006 165.246,108.475 161.246,108.475 161.246,103.006 ; 161.246,121.772 165.246,121.772 165.246,127.241 161.246,127.241 161.246,121.772
  lines w0.254: 81.089,85.979 cw(c82.009,79.257) 88.789,78.979 ; 81.089,139.979 ccw(c82.009,146.701) 88.789,146.979 ; 81.703,139.923 ccw(c81.941,139.074) 81.089,139.3 81.088,86.66 ccw(c81.942,86.886) 81.704,86.036 ; 88.784,79.603 ccw(c89.637,79.83) 89.4,78.98 156.777,78.98 ccw(c156.539,79.83) 157.393,79.603 ; 88.784,146.355 cw(c89.638,146.128) 89.4,146.979 156.777,146.979 cw(c156.539,146.129) 157.393,146.356 ; 157.389,78.979 cw(c164.168,79.257) 165.089,85.979 ; 157.389,146.979 ccw(c164.168,146.701) 165.089,139.979 ; 164.474,86.036 ccw(c164.236,86.885) 165.088,86.66 165.088,139.297 ccw(c164.236,139.072) 164.474,139.921

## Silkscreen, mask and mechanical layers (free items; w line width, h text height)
Mechanical Layer:
  circle w0.025: c85.141,81.991 r3
  circle w0.025: c161.141,143.991 r3
  circle w0.025: c161.141,81.991 r3
  circle w0.025: c85.141,143.991 r3
  circle w0.025: c97.968,128.981 r5.5
  circle w0.025: c148.387,128.981 r5.5
  lines w0.025: 81.057,103.067 81.057,102.165 82.011,103.067 81.057,103.067 ; 81.057,103.067 81.057,103.067 ; 81.057,121.813 81.057,120.91 82.011,121.813 81.057,121.813 ; 81.057,121.813 81.057,121.813 ; 81.083,108.438 81.985,108.438 81.083,109.392 81.083,108.438 ; 81.083,108.438 81.083,108.438 ; 81.089,127.203 81.991,127.203 81.089,128.158 81.089,127.203 ; 81.089,127.203 81.089,127.203 ; 109.342,78.949 109.342,79.852 108.387,78.949 109.342,78.949 ; 109.342,78.949 109.342,78.949 ; 113.239,78.923 114.142,78.923 113.239,79.878 113.239,78.923 ; 113.239,78.923 113.239,78.923 ; 161.697,106.217 160.794,106.217 161.697,105.263 161.697,106.217 ; 161.697,106.217 161.697,106.217 ; 161.723,124.055 161.723,124.958 160.769,124.055 161.723,124.055 ; 161.723,124.055 161.723,124.055 ; 165.094,103.042 164.191,103.042 165.094,102.088 165.094,103.042 ; 165.094,103.042 165.094,103.042 ; 165.12,127.209 165.12,128.112 164.166,127.209 165.12,127.209 ; 165.12,127.209 165.12,127.209 ; 81.014,103.006 85.014,103.006 85.014,108.475 81.014,108.475 81.014,103.006 ; 81.014,121.772 85.014,121.772 85.014,127.241 81.014,127.241 81.014,121.772 ; 83.214,81.991 cw(c85.141,81.991) 87.068,81.991 cw(c85.141,81.991) 83.214,81.991 ; 83.214,143.991 cw(c85.141,143.991) 87.068,143.991 cw(c85.141,143.991) 83.214,143.991 ; 109.303,78.853 113.303,78.853 113.303,84.322 109.303,84.322 109.303,78.853 ; 153.919,115.138 ccw(c163.246,115.138) 161.218,106.034 ccw(c161.246,106.158) 161.246,106.031 ccw(c161.246,106.158) 161.338,106.07 162.743,106.07 165.088,108.416 165.088,121.728 162.694,124.123 161.373,124.123 ccw(c161.246,124.118) 161.246,124.245 ccw(c161.246,124.118) 161.218,124.242 ccw(c163.246,115.138) 153.919,115.138 ; 159.214,81.991 cw(c161.141,81.991) 163.068,81.991 cw(c161.141,81.991) 159.214,81.991 ; 159.214,143.991 cw(c161.141,143.991) 163.068,143.991 cw(c161.141,143.991) 159.214,143.991 ; 161.246,103.006 165.246,103.006 165.246,108.475 161.246,108.475 161.246,103.006 ; 161.246,121.772 165.246,121.772 165.246,127.241 161.246,127.241 161.246,121.772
